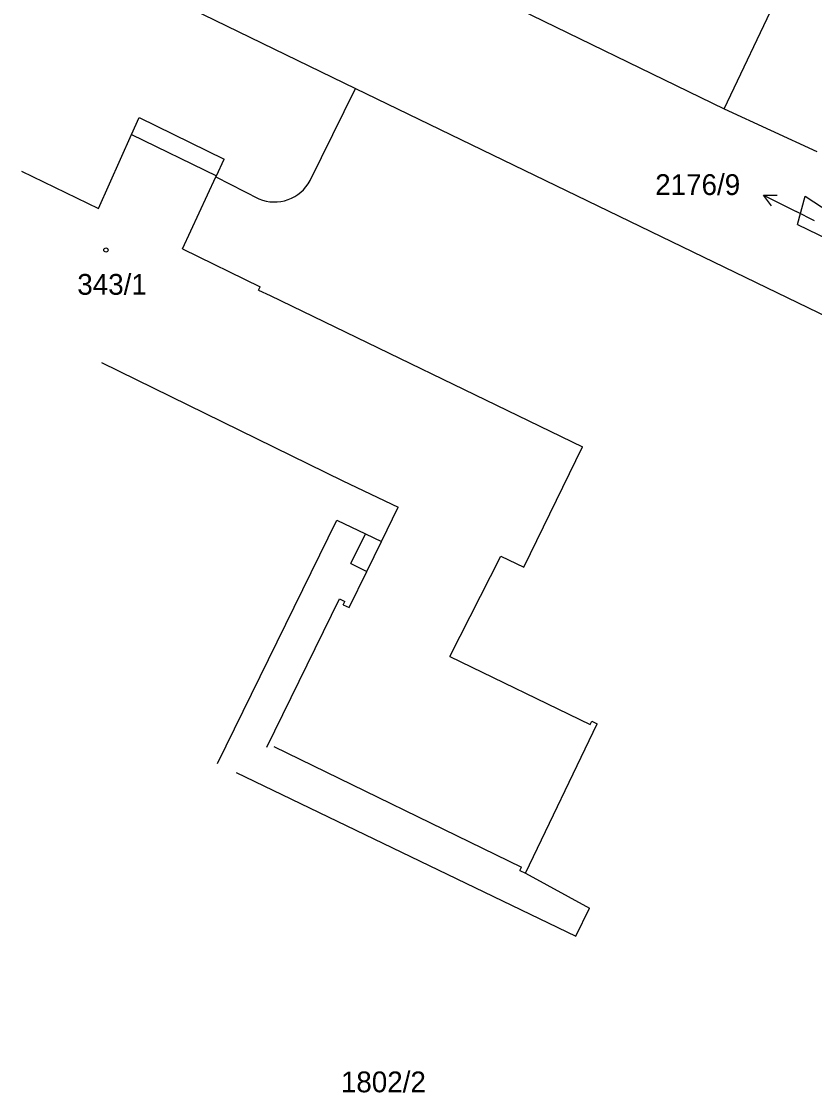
# Model space of a CAD drawing. Extents: x -763205 to -760228, y -1155311 to -1152844.
# Drawn here: x -762251 to -762186.1, y -1155107.7 to -1155020 of the extents above; entities that cross this region are included whole.
import ezdxf

# ---------------------------------------------------------------- set-up
doc = ezdxf.new("R2010")
doc.units = 0
for name, color, linetype in [('Vrstva 1', 7, 'Continuous'), ('Vrstva 16', 7, 'Continuous'), ('Vrstva 18', 7, 'Continuous'), ('Vrstva 19', 7, 'Continuous'), ('Vrstva 25', 7, 'Continuous'), ('Vrstva 4', 7, 'Continuous'), ('Vrstva 6', 7, 'Continuous')]:
    doc.layers.add(name, color=color, linetype=linetype)

msp = doc.modelspace()

# ---------------------------------------------------------------- linework, layer by layer
at = {"layer": 'Vrstva 1'}
for p, q in [((-762193.51, -1155027.17), (-762178.61, -1154995.87)), ((-762243.33, -1155015.92), (-762223.64, -1155025.5)), ((-762215.3, -1155016.55), (-762193.51, -1155027.17)), ((-762227.35, -1155033.04), (-762223.64, -1155025.5)), ((-762223.64, -1155025.5), (-762189.2, -1155042.19)), ((-762193.51, -1155027.17), (-762185.92, -1155030.67)), ((-762237.81, -1155038.62), (-762235.07, -1155032.74)), ((-762235.07, -1155032.74), (-762231.56, -1155034.53)), ((-762237.81, -1155038.62), (-762231.44, -1155041.73)), ((-762231.57, -1155042), (-762231.44, -1155041.73)), ((-762231.57, -1155042), (-762230.64, -1155042.45)), ((-762189.2, -1155042.19), (-762173.1, -1155049.99)), ((-762230.64, -1155042.45), (-762205.1, -1155054.82)), ((-762244.42, -1155047.92), (-762224.7, -1155057.6)), ((-762209.89, -1155064.66), (-762205.1, -1155054.82)), ((-762224.7, -1155057.6), (-762220.15, -1155059.77)), ((-762221.53, -1155062.58), (-762220.15, -1155059.77)), ((-762234.93, -1155080.74), (-762225.19, -1155060.82)), ((-762225.19, -1155060.82), (-762222.83, -1155061.95)), ((-762222.83, -1155061.95), (-762221.53, -1155062.58)), ((-762215.93, -1155071.98), (-762211.77, -1155063.77)), ((-762211.77, -1155063.77), (-762209.89, -1155064.66)), ((-762215.93, -1155071.98), (-762204.46, -1155077.53)), ((-762204.46, -1155077.53), (-762204.33, -1155077.26)), ((-762204.33, -1155077.26), (-762203.88, -1155077.48)), ((-762209.76, -1155089.7), (-762203.88, -1155077.48)), ((-762233.41, -1155081.47), (-762205.64, -1155094.86)), ((-762209.76, -1155089.7), (-762204.51, -1155092.57)), ((-762205.64, -1155094.86), (-762204.51, -1155092.57))]:
    msp.add_line(p, q, dxfattribs=at)
msp.add_arc((-762230.281, -1155031.452), 3.334, 247.43539, 331.54431, dxfattribs=at)
at = {"layer": 'Vrstva 16'}
for p in [(-762190.294, -1155034.219), (-762186.12, -1155036.34)]:
    msp.add_line(p, (-762187.62, -1155035.58), dxfattribs=at)
msp.add_lwpolyline([(-762189.629, -1155035.118), (-762190.294, -1155034.219), (-762189.176, -1155034.227)], dxfattribs=at)
at = {"layer": 'Vrstva 25'}
msp.add_circle((-762244.06, -1155038.72), 0.175, dxfattribs=at)
at = {"layer": 'Vrstva 4'}
for p, q in [((-762241.97, -1155029.26), (-762241.35, -1155027.87)), ((-762241.35, -1155027.87), (-762234.39, -1155031.28)), ((-762244.67, -1155035.31), (-762241.97, -1155029.26)), ((-762241.97, -1155029.26), (-762235.02, -1155032.64)), ((-762235.02, -1155032.64), (-762234.39, -1155031.28)), ((-762250.97, -1155032.28), (-762244.67, -1155035.31)), ((-762235.07, -1155032.74), (-762235.02, -1155032.64)), ((-762224.03, -1155064.38), (-762222.83, -1155061.95)), ((-762222.73, -1155065.02), (-762221.53, -1155062.58)), ((-762224.18, -1155067.97), (-762222.73, -1155065.02)), ((-762224.03, -1155064.38), (-762222.73, -1155065.02)), ((-762230.91, -1155079.39), (-762224.97, -1155067.26)), ((-762224.97, -1155067.26), (-762224.52, -1155067.47)), ((-762224.65, -1155067.74), (-762224.52, -1155067.47)), ((-762224.65, -1155067.74), (-762224.18, -1155067.97)), ((-762230.34, -1155079.33), (-762210.08, -1155089.21)), ((-762210.21, -1155089.48), (-762210.08, -1155089.21)), ((-762210.21, -1155089.48), (-762209.76, -1155089.7))]:
    msp.add_line(p, q, dxfattribs=at)
at = {"layer": 'Vrstva 6'}
for p, q in [((-762187.51, -1155036.64), (-762186.89, -1155034.31)), ((-762186.89, -1155034.31), (-762171.56, -1155044.37)), ((-762187.51, -1155036.64), (-762171.56, -1155044.37))]:
    msp.add_line(p, q, dxfattribs=at)

# ---------------------------------------------------------------- texts
at = {"layer": 'Vrstva 16'}
msp.add_text('2176/9', height=1.7, dxfattribs=at).set_placement((-762199.144, -1155034.22))
at = {"layer": 'Vrstva 18'}
msp.add_text('1802/2', height=1.7, dxfattribs=at).set_placement((-762224.847, -1155107.63))
at = {"layer": 'Vrstva 19'}
msp.add_text('343/1', height=1.7, dxfattribs=at).set_placement((-762246.403, -1155042.38))

doc.saveas('drawing.dxf')
